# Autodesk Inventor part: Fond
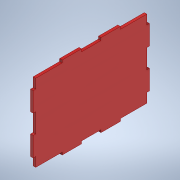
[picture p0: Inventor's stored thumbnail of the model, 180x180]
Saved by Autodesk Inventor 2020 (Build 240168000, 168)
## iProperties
Created: 2023-12
Part Number: Fond
Material: Générique
Document SubType Name: Modeling
Designer: bruno
Density: 1 g/cm^3
Appearance: Rouge
Author: bruno
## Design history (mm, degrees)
sketch "Esquisse1"
  geometry: L1 (59.938, 165)-(82.812, 165); L2 (59.938, 162)-(59.938, 165); L3 (37.062, 162)-(59.938, 162); L4 (37.062, 165)-(37.062, 162); L5 (14.188, 165)-(37.062, 165); L6 (14.188, 162)-(14.188, 165); L7 (0, 162)-(14.188, 162); L8 (82.812, 165)-(82.812, 162); L9 (0, 182.812)-(0, 162); L10 (97, 318)-(0, 318); L11 (97, 297.188)-(97, 318); L12 (94, 297.188)-(97, 297.188); L13 (94, 274.312)-(94, 297.188); L14 (97, 274.312)-(94, 274.312); L15 (97, 251.438)-(97, 274.312); L16 (94, 251.438)-(97, 251.438); L17 (94, 228.563)-(94, 251.438); L18 (97, 228.563)-(94, 228.563); L19 (97, 205.688)-(97, 228.563); L20 (94, 205.688)-(97, 205.688); L21 (94, 182.812)-(94, 205.688); L22 (3, 205.688)-(3, 182.812); L23 (0, 205.688)-(3, 205.688); L24 (0, 228.563)-(0, 205.688); L25 (3, 228.563)-(0, 228.563); L26 (3, 182.812)-(0, 182.812); L27 (0, 318)-(0, 297.188); L28 (3, 251.438)-(3, 228.563); L29 (0, 251.438)-(3, 251.438); L30 (0, 274.312)-(0, 251.438); L31 (3, 274.312)-(0, 274.312); L32 (3, 297.188)-(3, 274.312); L33 (0, 297.188)-(3, 297.188); L34 (97, 182.812)-(94, 182.812); L35 (97, 162)-(97, 182.812); L36 (82.812, 162)-(97, 162); L37 (337, 82.938)-(337, 105.812); L38 (243, 60.063)-(240, 60.063); L39 (243, 82.938)-(243, 60.063); L40 (240, 82.938)-(243, 82.938); L41 (240, 105.812)-(240, 82.938); L42 (243, 105.812)-(240, 105.812); L43 (243, 137)-(243, 105.812); L44 (337, 105.812)-(334, 105.812); L45 (334, 105.812)-(334, 128.688); L46 (334, 128.688)-(334, 137); L47 (334, 137)-(322.812, 137); L48 (322.812, 137)-(322.812, 140); L49 (322.812, 140)-(299.938, 140); L50 (299.938, 140)-(299.938, 137); L51 (299.938, 137)-(277.062, 137); L52 (277.062, 137)-(277.062, 140); L53 (277.062, 140)-(254.188, 140); L54 (254.188, 140)-(254.188, 137); L55 (254.188, 137)-(243, 137); L56 (254.188, 6)-(254.188, 3); L57 (243, 6)-(254.188, 6); L58 (243, 14.313)-(243, 6); L59 (243, 37.188)-(243, 14.313); L60 (240, 37.188)-(243, 37.188); L61 (240, 60.063)-(240, 37.188); L62 (277.062, 3)-(277.062, 6); L63 (277.062, 6)-(299.938, 6); L64 (299.938, 6)-(299.938, 3)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; 39 further points
  constraints: 368 end point
extrude "Extrusion1" new body sketch "Esquisse1" distance "d0" = 3; taper "d1" = 0 deg
sketch "Esquisse2"
  geometry: L1 (-137, 254.188)-(-137, 243) reference; L2 (-137, 243)-(-105.812, 243) reference; L3 (-105.812, 243)-(-105.812, 240) reference; L4 (-105.812, 240)-(-82.938, 240) reference; L5 (-82.938, 240)-(-82.938, 243) reference; L6 (-82.938, 243)-(-60.063, 243) reference; L7 (-60.063, 243)-(-60.063, 240) reference; L8 (-60.063, 240)-(-37.188, 240) reference; L9 (-37.188, 240)-(-37.188, 243) reference; L10 (-37.188, 243)-(-6, 243) reference; L11 (-6, 243)-(-6, 254.188) reference; L12 (-6, 254.188)-(-3, 254.188) reference; L13 (-3, 254.188)-(-3, 277.062) reference; L14 (-3, 277.062)-(-6, 277.062) reference; L15 (-6, 277.062)-(-6, 299.938) reference; L16 (-6, 299.938)-(-3, 299.938) reference; L17 (-3, 299.938)-(-3, 322.812) reference; L18 (-3, 322.812)-(-6, 322.812) reference; L19 (-6, 322.812)-(-6, 334) reference; L20 (-6, 334)-(-37.188, 334) reference; L21 (-37.188, 334)-(-37.188, 337) reference; L22 (-37.188, 337)-(-60.063, 337) reference; L23 (-60.063, 337)-(-60.063, 334) reference; L24 (-60.063, 334)-(-82.938, 334) reference; L25 (-82.938, 334)-(-82.938, 337) reference; L26 (-82.938, 337)-(-105.812, 337) reference; L27 (-105.812, 337)-(-105.812, 334) reference; L28 (-105.812, 334)-(-137, 334) reference; L29 (-137, 334)-(-137, 322.812) reference; L30 (-137, 322.812)-(-140, 322.812) reference; L31 (-140, 322.812)-(-140, 299.938) reference; L32 (-140, 299.938)-(-137, 299.938) reference; L33 (-137, 299.938)-(-137, 277.062) reference; L34 (-137, 277.062)-(-140, 277.062) reference; L35 (-140, 277.062)-(-140, 254.188) reference; L36 (-140, 254.188)-(-137, 254.188) reference; L37 (-137, 299.938)-(-137, 277.062) reference; L38 (-137, 299.837)-(-140, 299.837); L39 (-140, 299.837)-(-140, 322.912); L40 (-140, 322.912)-(-137, 322.912); L41 (-137, 322.912)-(-137, 299.837); L42 (-137, 277.163)-(-140, 277.163); L43 (-140, 277.163)-(-140, 254.088); L44 (-140, 254.088)-(-137, 254.088); L45 (-137, 254.088)-(-137, 277.163); 9 further points
  constraints: 16 end point, 4 parallel, 2 horizontal, 2 perpendicular, 2 point on line
  dimensions: "d2" = 0.1 distance between parallel lines of L32 L38; "d3" = 0.1 distance between parallel lines of L40 L30; "d4" = 0.1 distance between parallel lines of L36 L44; "d5" = 0.1 distance between parallel lines of L42 L34
extrude "Extrusion2" join sketch "Esquisse2" stored distance "d6" = 10; taper "d7" = 0 deg
pattern_linear "Réseau rectangulaire1" dims "d10" = 134
node "Solide1"
node "Boucle projetée1"
